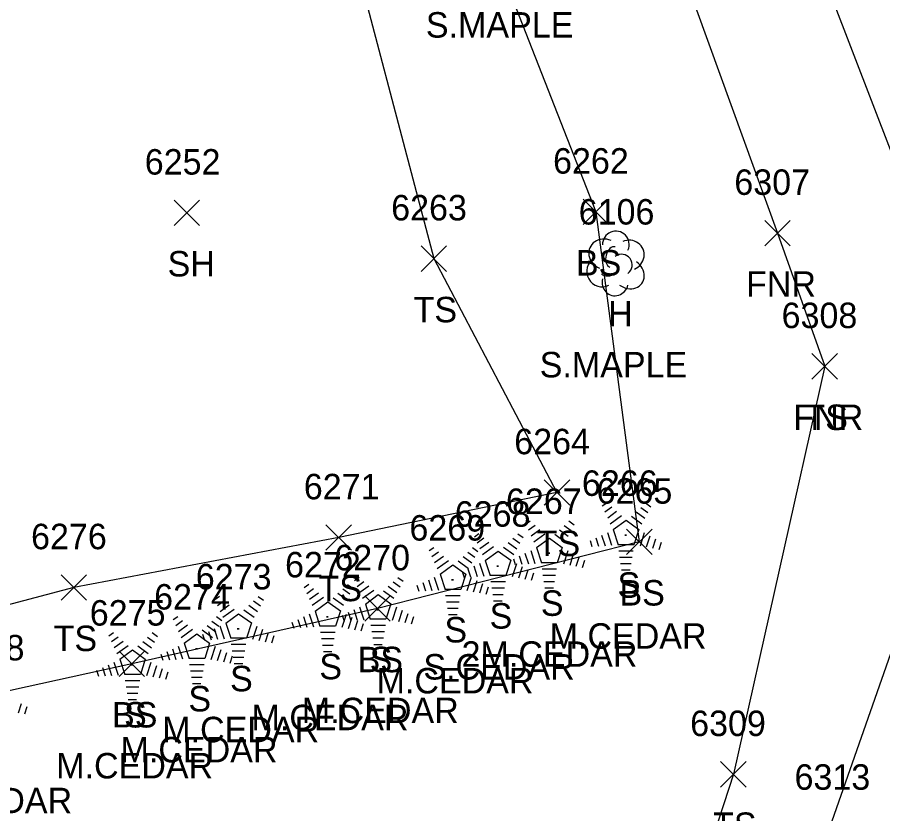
# Model space of a CAD drawing. Extents: x 1472233 to 1475777, y 540726 to 543442.
# Drawn here: x 1472443 to 1472511, y 541606.1 to 541668.7 of the extents above; entities that cross this region are included whole.
import ezdxf

# ---------------------------------------------------------------- set-up
doc = ezdxf.new("R2010")
doc.units = 0
for name, color, linetype in [('L_A', 7, 'Continuous'), ('L_C', 7, 'Continuous'), ('L_I', 7, 'Continuous'), ('L_TIC', 7, 'Continuous'), ('LELB', 7, 'Continuous'), ('LFNC', 7, 'Continuous'), ('LTC', 7, 'Continuous'), ('LTD', 7, 'Continuous'), ('R_I', 7, 'Continuous'), ('RDG', 7, 'Continuous')]:
    doc.layers.add(name, color=color, linetype=linetype)

msp = doc.modelspace()

# ---------------------------------------------------------------- linework, layer by layer
at = {"layer": 'L_TIC'}
for points in [[(1472455.369, 541652.318), (1472457.369, 541654.318)], [(1472457.369, 541652.318), (1472455.369, 541654.318)], [(1472487.5, 541652.393), (1472489.5, 541654.393)], [(1472489.5, 541652.393), (1472487.5, 541654.393)], [(1472501.774, 541650.725), (1472503.774, 541652.725)], [(1472503.774, 541650.725), (1472501.774, 541652.725)], [(1472474.778, 541648.719), (1472476.778, 541650.719)], [(1472476.778, 541648.719), (1472474.778, 541650.719)], [(1472505.489, 541640.264), (1472507.489, 541642.264)], [(1472507.489, 541640.264), (1472505.489, 541642.264)], [(1472505.489, 541640.264), (1472507.489, 541642.264)], [(1472507.489, 541640.264), (1472505.489, 541642.264)], [(1472484.45, 541630.36), (1472486.45, 541632.36)], [(1472486.45, 541630.36), (1472484.45, 541632.36)], [(1472467.299, 541626.822), (1472469.299, 541628.822)], [(1472469.299, 541626.822), (1472467.299, 541628.822)], [(1472490.922, 541626.481), (1472492.922, 541628.481)], [(1472492.922, 541626.481), (1472490.922, 541628.481)], [(1472446.489, 541622.903), (1472448.489, 541624.903)], [(1472448.489, 541622.903), (1472446.489, 541624.903)], [(1472470.349, 541621.246), (1472472.349, 541623.246)], [(1472472.349, 541621.246), (1472470.349, 541623.246)], [(1472451.049, 541616.906), (1472453.049, 541618.906)], [(1472453.049, 541616.906), (1472451.049, 541618.906)], [(1472498.312, 541608.233), (1472500.312, 541610.233)], [(1472500.312, 541608.233), (1472498.312, 541610.233)]]:
    msp.add_lwpolyline(points, dxfattribs=at)
at = {"layer": 'LELB'}
for points in [[(1472448.097, 541812.754), (1472448.348, 541808.89), (1472456.833, 541789.055), (1472474.313, 541748.227), (1472493.036, 541702.804), (1472494.569, 541702.635), (1472518.001, 541641.77), (1472527.768, 541616.945), (1472533.943, 541611.957), (1472541.348, 541598.757), (1472552.579, 541572.187), (1472569.893, 541532.316), (1472586.676, 541490.501), (1472602.946, 541447.471), (1472614.294, 541413.724), (1472616.337, 541394.529)], [(1472456.355, 541750.745), (1472468.133, 541714.403), (1472477.981, 541680.268), (1472488.5, 541653.393), (1472491.922, 541627.481), (1472471.349, 541622.246), (1472452.049, 541617.906), (1472420.205, 541610.928)], [(1472456.355, 541750.745), (1472459.339, 541711.408), (1472468.15, 541678.645), (1472475.778, 541649.719), (1472485.45, 541631.36), (1472468.299, 541627.822), (1472447.489, 541623.903), (1472426.411, 541618.317)], [(1472506.489, 541641.264), (1472499.312, 541609.233), (1472486.866, 541571.029)]]:
    msp.add_lwpolyline(points, dxfattribs=at)
at = {"layer": 'LFNC'}
msp.add_lwpolyline([(1472436.391, 541801.492), (1472440.785, 541802.077), (1472447.251, 541803.401), (1472449.765, 541795.885), (1472456.456, 541773.785), (1472468.551, 541746.277), (1472485.593, 541698.937), (1472485.509, 541699.297), (1472502.774, 541651.725), (1472506.489, 541641.264)], dxfattribs=at)
at = {"layer": 'LTC'}
for p, q in [((1472489.016, 541630.3), (1472489.371, 541630.558)), ((1472492.415, 541630.541), (1472492.834, 541630.236)), ((1472489.226, 541629.835), (1472489.755, 541630.219)), ((1472489.436, 541629.369), (1472490.139, 541629.88)), ((1472491.673, 541629.844), (1472492.352, 541629.35)), ((1472492.043, 541630.192), (1472492.593, 541629.793)), ((1472482.994, 541628.88), (1472483.348, 541629.137)), ((1472486.392, 541629.12), (1472486.811, 541628.815)), ((1472489.645, 541628.903), (1472490.523, 541629.541)), ((1472489.87, 541628.448), (1472490.881, 541629.183)), ((1472490.881, 541629.183), (1472491.878, 541628.458)), ((1472491.301, 541629.496), (1472492.111, 541628.907)), ((1472483.203, 541628.414), (1472483.733, 541628.798)), ((1472483.413, 541627.948), (1472484.117, 541628.46)), ((1472485.65, 541628.423), (1472486.329, 541627.93)), ((1472486.021, 541628.772), (1472486.57, 541628.373)), ((1472489.87, 541628.448), (1472490.257, 541627.255)), ((1472491.878, 541628.458), (1472491.487, 541627.255)), ((1472478.969, 541627.879), (1472479.323, 541628.137)), ((1472479.178, 541627.414), (1472479.707, 541627.798)), ((1472481.996, 541627.771), (1472482.545, 541627.372)), ((1472482.367, 541628.12), (1472482.786, 541627.815)), ((1472483.623, 541627.483), (1472484.501, 541628.12)), ((1472483.847, 541627.028), (1472484.859, 541627.762)), ((1472484.859, 541627.762), (1472485.856, 541627.037)), ((1472485.279, 541628.075), (1472486.088, 541627.486)), ((1472488.504, 541627.796), (1472488.716, 541627.145)), ((1472488.96, 541628.013), (1472489.231, 541627.177)), ((1472489.415, 541628.229), (1472489.746, 541627.21)), ((1472492.316, 541628.187), (1472491.978, 541627.147)), ((1472492.761, 541627.937), (1472492.473, 541627.052)), ((1472475.416, 541626.79), (1472475.771, 541627.047)), ((1472478.814, 541627.03), (1472479.234, 541626.725)), ((1472479.388, 541626.948), (1472480.092, 541627.459)), ((1472479.597, 541626.482), (1472480.476, 541627.12)), ((1472481.254, 541627.075), (1472482.063, 541626.486)), ((1472481.625, 541627.423), (1472482.304, 541626.929)), ((1472483.847, 541627.028), (1472484.234, 541625.834)), ((1472485.856, 541627.037), (1472485.465, 541625.834)), ((1472488.049, 541627.58), (1472488.201, 541627.112)), ((1472491.487, 541627.255), (1472490.257, 541627.255)), ((1472493.205, 541627.687), (1472492.968, 541626.957)), ((1472493.649, 541627.436), (1472493.463, 541626.862)), ((1472475.626, 541626.324), (1472476.155, 541626.708)), ((1472475.835, 541625.858), (1472476.539, 541626.37)), ((1472478.072, 541626.333), (1472478.752, 541625.84)), ((1472478.443, 541626.682), (1472478.993, 541626.283)), ((1472479.822, 541626.027), (1472480.834, 541626.762)), ((1472480.834, 541626.762), (1472481.831, 541626.037)), ((1472482.482, 541626.375), (1472482.693, 541625.724)), ((1472482.937, 541626.592), (1472483.208, 541625.757)), ((1472483.393, 541626.808), (1472483.723, 541625.789)), ((1472486.293, 541626.766), (1472485.955, 541625.727)), ((1472486.738, 541626.516), (1472486.45, 541625.631)), ((1472491.449, 541626.755), (1472490.304, 541626.755)), ((1472476.045, 541625.393), (1472476.923, 541626.03)), ((1472476.269, 541624.938), (1472477.281, 541625.672)), ((1472477.281, 541625.672), (1472478.278, 541624.947)), ((1472477.701, 541625.985), (1472478.511, 541625.396)), ((1472479.367, 541625.808), (1472479.698, 541624.789)), ((1472479.822, 541626.027), (1472480.209, 541624.834)), ((1472481.831, 541626.037), (1472481.439, 541624.834)), ((1472482.268, 541625.766), (1472481.93, 541624.726)), ((1472482.026, 541626.159), (1472482.178, 541625.691)), ((1472485.465, 541625.834), (1472484.234, 541625.834)), ((1472487.183, 541626.266), (1472486.945, 541625.536)), ((1472487.627, 541626.015), (1472487.44, 541625.441)), ((1472491.365, 541626.255), (1472490.377, 541626.255)), ((1472491.281, 541625.755), (1472490.45, 541625.755)), ((1472478.001, 541625.158), (1472478.153, 541624.691)), ((1472478.457, 541625.375), (1472478.668, 541624.723)), ((1472478.912, 541625.592), (1472479.183, 541624.756)), ((1472482.713, 541625.516), (1472482.425, 541624.631)), ((1472483.157, 541625.266), (1472482.92, 541624.536)), ((1472483.602, 541625.015), (1472483.415, 541624.441)), ((1472485.426, 541625.334), (1472484.282, 541625.334)), ((1472491.198, 541625.255), (1472490.523, 541625.255)), ((1472469.544, 541624.454), (1472469.899, 541624.711)), ((1472469.754, 541623.989), (1472470.283, 541624.373)), ((1472472.571, 541624.346), (1472473.121, 541623.947)), ((1472472.943, 541624.694), (1472473.362, 541624.39)), ((1472475.359, 541624.502), (1472475.631, 541623.667)), ((1472475.815, 541624.718), (1472476.146, 541623.699)), ((1472476.269, 541624.938), (1472476.657, 541623.744)), ((1472478.278, 541624.947), (1472477.887, 541623.744)), ((1472478.716, 541624.676), (1472478.378, 541623.637)), ((1472479.16, 541624.426), (1472478.873, 541623.541)), ((1472481.439, 541624.834), (1472480.209, 541624.834)), ((1472481.401, 541624.334), (1472480.257, 541624.334)), ((1472485.343, 541624.834), (1472484.354, 541624.834)), ((1472485.259, 541624.334), (1472484.427, 541624.334)), ((1472465.589, 541623.901), (1472465.943, 541624.158)), ((1472465.798, 541623.435), (1472466.328, 541623.819)), ((1472468.616, 541623.793), (1472469.166, 541623.393)), ((1472468.987, 541624.141), (1472469.406, 541623.836)), ((1472469.964, 541623.523), (1472470.667, 541624.034)), ((1472470.173, 541623.057), (1472471.052, 541623.695)), ((1472471.829, 541623.649), (1472472.639, 541623.061)), ((1472472.201, 541623.998), (1472472.88, 541623.504)), ((1472474.449, 541624.069), (1472474.601, 541623.601)), ((1472474.904, 541624.285), (1472475.116, 541623.634)), ((1472477.887, 541623.744), (1472476.657, 541623.744)), ((1472479.605, 541624.176), (1472479.368, 541623.446)), ((1472480.049, 541623.925), (1472479.862, 541623.351)), ((1472481.317, 541623.834), (1472480.329, 541623.834)), ((1472485.175, 541623.834), (1472484.5, 541623.834)), ((1472458.574, 541622.955), (1472458.929, 541623.212)), ((1472461.972, 541623.195), (1472462.391, 541622.891)), ((1472466.008, 541622.969), (1472466.712, 541623.481)), ((1472466.218, 541622.503), (1472467.096, 541623.141)), ((1472467.874, 541623.096), (1472468.683, 541622.507)), ((1472468.245, 541623.444), (1472468.924, 541622.951)), ((1472470.398, 541622.602), (1472471.409, 541623.336)), ((1472471.409, 541623.336), (1472472.406, 541622.611)), ((1472477.849, 541623.244), (1472476.704, 541623.244)), ((1472481.234, 541623.334), (1472480.402, 541623.334)), ((1472458.784, 541622.49), (1472459.313, 541622.874)), ((1472458.993, 541622.024), (1472459.697, 541622.535)), ((1472461.23, 541622.499), (1472461.909, 541622.005)), ((1472461.601, 541622.847), (1472462.151, 541622.448)), ((1472466.442, 541622.048), (1472467.454, 541622.783)), ((1472467.454, 541622.783), (1472468.451, 541622.058)), ((1472469.943, 541622.383), (1472470.274, 541621.364)), ((1472470.398, 541622.602), (1472470.785, 541621.409)), ((1472472.406, 541622.611), (1472472.015, 541621.409)), ((1472472.844, 541622.341), (1472472.506, 541621.301)), ((1472477.765, 541622.744), (1472476.777, 541622.744)), ((1472481.15, 541622.834), (1472480.475, 541622.834)), ((1472455.299, 541621.375), (1472455.654, 541621.632)), ((1472458.697, 541621.615), (1472459.117, 541621.311)), ((1472459.203, 541621.558), (1472460.081, 541622.196)), ((1472459.427, 541621.103), (1472460.439, 541621.837)), ((1472460.439, 541621.837), (1472461.436, 541621.112)), ((1472460.859, 541622.15), (1472461.669, 541621.562)), ((1472465.532, 541621.613), (1472465.803, 541620.778)), ((1472465.988, 541621.829), (1472466.318, 541620.81)), ((1472466.442, 541622.048), (1472466.829, 541620.855)), ((1472468.451, 541622.058), (1472468.06, 541620.855)), ((1472468.888, 541621.787), (1472468.551, 541620.748)), ((1472468.577, 541621.733), (1472468.729, 541621.265)), ((1472469.032, 541621.95), (1472469.244, 541621.298)), ((1472469.488, 541622.166), (1472469.759, 541621.331)), ((1472473.289, 541622.09), (1472473.001, 541621.206)), ((1472473.733, 541621.84), (1472473.496, 541621.111)), ((1472474.177, 541621.59), (1472473.991, 541621.016)), ((1472477.681, 541622.244), (1472476.849, 541622.244)), ((1472477.597, 541621.744), (1472476.922, 541621.744)), ((1472455.509, 541620.91), (1472456.038, 541621.294)), ((1472455.718, 541620.444), (1472456.422, 541620.955)), ((1472457.955, 541620.919), (1472458.635, 541620.425)), ((1472458.326, 541621.267), (1472458.876, 541620.868)), ((1472459.427, 541621.103), (1472459.814, 541619.91)), ((1472461.436, 541621.112), (1472461.045, 541619.91)), ((1472464.621, 541621.18), (1472464.774, 541620.712)), ((1472465.077, 541621.396), (1472465.288, 541620.745)), ((1472469.333, 541621.537), (1472469.046, 541620.652)), ((1472469.778, 541621.287), (1472469.541, 541620.557)), ((1472470.222, 541621.036), (1472470.035, 541620.462)), ((1472472.015, 541621.409), (1472470.785, 541621.409)), ((1472471.977, 541620.909), (1472470.832, 541620.909)), ((1472450.244, 541620.115), (1472450.599, 541620.372)), ((1472453.642, 541620.355), (1472454.062, 541620.05)), ((1472455.928, 541619.978), (1472456.806, 541620.616)), ((1472456.152, 541619.523), (1472457.164, 541620.257)), ((1472457.164, 541620.257), (1472458.161, 541619.532)), ((1472457.584, 541620.57), (1472458.394, 541619.982)), ((1472457.607, 541620.234), (1472457.759, 541619.766)), ((1472458.062, 541620.451), (1472458.274, 541619.799)), ((1472458.517, 541620.667), (1472458.789, 541619.832)), ((1472458.973, 541620.884), (1472459.304, 541619.865)), ((1472461.874, 541620.842), (1472461.536, 541619.802)), ((1472462.318, 541620.591), (1472462.031, 541619.707)), ((1472462.763, 541620.341), (1472462.526, 541619.612)), ((1472468.06, 541620.855), (1472466.829, 541620.855)), ((1472468.021, 541620.355), (1472466.877, 541620.355)), ((1472471.893, 541620.409), (1472470.905, 541620.409)), ((1472450.454, 541619.649), (1472450.983, 541620.033)), ((1472450.663, 541619.183), (1472451.367, 541619.695)), ((1472452.9, 541619.658), (1472453.58, 541619.165)), ((1472453.271, 541620.007), (1472453.821, 541619.608)), ((1472458.161, 541619.532), (1472457.77, 541618.33)), ((1472461.045, 541619.91), (1472459.814, 541619.91)), ((1472463.207, 541620.091), (1472463.02, 541619.517)), ((1472467.938, 541619.855), (1472466.949, 541619.855)), ((1472471.809, 541619.909), (1472470.978, 541619.909)), ((1472450.873, 541618.718), (1472451.751, 541619.355)), ((1472451.097, 541618.263), (1472452.109, 541618.997)), ((1472452.109, 541618.997), (1472453.106, 541618.272)), ((1472452.529, 541619.31), (1472453.339, 541618.721)), ((1472454.787, 541618.871), (1472454.999, 541618.219)), ((1472455.242, 541619.087), (1472455.514, 541618.252)), ((1472455.698, 541619.304), (1472456.029, 541618.285)), ((1472456.152, 541619.523), (1472456.54, 541618.33)), ((1472458.599, 541619.262), (1472458.261, 541618.222)), ((1472459.043, 541619.011), (1472458.756, 541618.127)), ((1472461.006, 541619.41), (1472459.862, 541619.41)), ((1472460.923, 541618.91), (1472459.934, 541618.91)), ((1472467.854, 541619.355), (1472467.022, 541619.355)), ((1472467.77, 541618.855), (1472467.095, 541618.855)), ((1472471.726, 541619.409), (1472471.051, 541619.409)), ((1472451.097, 541618.263), (1472451.485, 541617.069)), ((1472453.106, 541618.272), (1472452.715, 541617.069)), ((1472454.332, 541618.654), (1472454.484, 541618.186)), ((1472457.77, 541618.33), (1472456.54, 541618.33)), ((1472459.488, 541618.761), (1472459.251, 541618.032)), ((1472459.932, 541618.511), (1472459.745, 541617.937)), ((1472460.839, 541618.41), (1472460.007, 541618.41)), ((1472449.732, 541617.61), (1472449.944, 541616.959)), ((1472450.187, 541617.827), (1472450.459, 541616.992)), ((1472450.643, 541618.043), (1472450.974, 541617.024)), ((1472453.544, 541618.001), (1472453.206, 541616.962)), ((1472453.988, 541617.751), (1472453.701, 541616.866)), ((1472454.433, 541617.501), (1472454.196, 541616.771)), ((1472457.732, 541617.83), (1472456.587, 541617.83)), ((1472460.755, 541617.91), (1472460.08, 541617.91)), ((1472449.277, 541617.394), (1472449.429, 541616.926)), ((1472452.715, 541617.069), (1472451.485, 541617.069)), ((1472454.877, 541617.25), (1472454.69, 541616.676)), ((1472457.648, 541617.33), (1472456.66, 541617.33)), ((1472457.564, 541616.83), (1472456.732, 541616.83)), ((1472452.677, 541616.569), (1472451.532, 541616.569)), ((1472457.48, 541616.33), (1472456.805, 541616.33)), ((1472452.593, 541616.069), (1472451.605, 541616.069)), ((1472452.509, 541615.569), (1472451.677, 541615.569)), ((1472443.351, 541614.769), (1472443.114, 541614.039)), ((1472452.425, 541615.069), (1472451.75, 541615.069)), ((1472443.795, 541614.518), (1472443.608, 541613.944))]:
    msp.add_line(p, q, dxfattribs=at)
at = {"layer": 'LTD'}
msp.add_line((1472490.033, 541649.396), (1472490.033, 541649.396), dxfattribs=at)
msp.add_line((1472490.033, 541649.396), (1472490.033, 541649.396), dxfattribs=at)
msp.add_arc((1472490.08, 541650.83), 1.047, 335.52715, 180.95627, dxfattribs=at)
for centre, major_axis, ratio, start_param, end_param in [((1472489.241, 541650.062), (1.21, -0.512), 0.895232, 1.570796, 4.712389), ((1472491.075, 541649.979), (-1.141, -0.483), 0.949671, 1.570796, 4.712389), ((1472489.825, 541649.854), (-0.208, -0.792), 0.645439, 3.141593, 6.283185), ((1472490.533, 541649.229), (-0.5, 0.667), 0.989748, 3.141593, 6.283185), ((1472488.95, 541648.687), (0.584, -1.042), 0.959034, 3.141593, 6.283185), ((1472491.033, 541648.562), (-1.09, 0.792), 0.841452, 1.570796, 4.712389), ((1472490.033, 541647.896), (0.265, 1.061), 0.942809, 1.570796, 4.712389), ((1472489.575, 541648.646), (-0.625, -0.083), 0.423636, 0, 3.141593)]:
    msp.add_ellipse(centre, major_axis=major_axis, ratio=ratio, start_param=start_param, end_param=end_param, dxfattribs=at)
at = {"layer": 'RDG'}
msp.add_lwpolyline([(1472515.041, 541628.327), (1472506.859, 541605.018), (1472500.261, 541584.295), (1472490.718, 541567.191), (1472485.309, 541561.603)], dxfattribs=at)

# ---------------------------------------------------------------- texts
at = {"layer": 'L_A'}
for s, p in [('SH', (1472454.857, 541648.318)), ('BS', (1472486.941, 541648.393)), ('FNR', (1472500.31, 541646.725)), ('TS', (1472474.187, 541644.719)), ('H', (1472489.466, 541644.396)), ('FNR', (1472504.024, 541636.264)), ('TS', (1472504.898, 541636.264)), ('TS', (1472483.859, 541626.36)), ('S', (1472490.207, 541623.092)), ('TS', (1472466.709, 541622.822)), ('BS', (1472490.363, 541622.481)), ('S', (1472484.184, 541621.671)), ('S', (1472480.159, 541620.671)), ('S', (1472476.607, 541619.581)), ('TS', (1472445.899, 541618.903)), ('BS', (1472469.79, 541617.246)), ('S', (1472470.735, 541617.246)), ('S', (1472466.78, 541616.692)), ('S', (1472459.765, 541615.747)), ('S', (1472456.49, 541614.167)), ('BS', (1472450.49, 541612.906)), ('S', (1472451.435, 541612.906)), ('TS', (1472497.721, 541604.233))]:
    msp.add_text(s, height=2, dxfattribs=at).set_placement(p)
at = {"layer": 'L_C'}
for s, p in [('S.MAPLE', (1472475.151, 541667.073)), ('S.MAPLE', (1472484.096, 541640.396)), ('M.CEDAR', (1472484.876, 541619.092)), ('2M.CEDAR', (1472477.956, 541617.671)), ('S.CEDAR', (1472474.955, 541616.671)), ('M.CEDAR', (1472471.276, 541615.581)), ('M.CEDAR', (1472465.404, 541613.246)), ('M.CEDAR', (1472461.449, 541612.692)), ('M.CEDAR', (1472454.434, 541611.747)), ('M.CEDAR', (1472451.159, 541610.167)), ('M.CEDAR', (1472446.104, 541608.906)), ('M.CEDAR', (1472435.022, 541606.174))]:
    msp.add_text(s, height=2, dxfattribs=at).set_placement(p)
at = {"layer": 'L_I'}
for s, p in [('6252', (1472453.062, 541656.318)), ('6262', (1472485.146, 541656.393)), ('6307', (1472499.388, 541654.725)), ('6263', (1472472.424, 541652.719)), ('6106', (1472487.159, 541652.396)), ('6308', (1472503.103, 541644.264)), ('6308', (1472503.103, 541644.264)), ('6264', (1472482.095, 541634.36)), ('6271', (1472465.559, 541630.822)), ('6266', (1472487.412, 541631.092)), ('6265', (1472488.568, 541630.481)), ('6267', (1472481.444, 541629.671)), ('6268', (1472477.419, 541628.671)), ('6269', (1472473.859, 541627.581)), ('6276', (1472444.127, 541626.903)), ('6270', (1472467.956, 541625.246)), ('6270', (1472467.956, 541625.246)), ('6272', (1472464.087, 541624.692)), ('6273', (1472457.072, 541623.747)), ('6274', (1472453.797, 541622.167)), ('6275', (1472448.742, 541620.906)), ('6275', (1472448.742, 541620.906)), ('6278', (1472437.66, 541618.174)), ('6309', (1472495.918, 541612.233))]:
    msp.add_text(s, height=2, dxfattribs=at).set_placement(p)
at = {"layer": 'LTC'}
for p in [(1472490.764, 541628.196), (1472484.741, 541626.775), (1472480.716, 541625.775), (1472477.164, 541624.685), (1472467.336, 541621.796), (1472471.292, 541622.35), (1472460.321, 541620.851), (1472457.047, 541619.271), (1472451.992, 541618.01)]:
    msp.add_text('.', height=1.037, rotation=270, dxfattribs=at).set_placement(p)
at = {"layer": 'R_I'}
msp.add_text('6313', height=2, dxfattribs=at).set_placement((1472504.119, 541608.018))

doc.saveas('drawing.dxf')
